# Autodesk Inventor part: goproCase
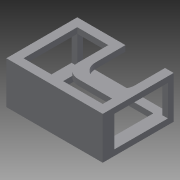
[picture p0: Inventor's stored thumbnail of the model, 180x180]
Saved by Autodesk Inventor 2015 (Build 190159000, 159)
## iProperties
Created: 2015-02
Part Number: goproCase
Material: Generic
Document SubType Name: Modeling
Designer: sungeun
Density: 1 g/cm^3
Appearance: Default
Author: sungeun
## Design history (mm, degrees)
sketch "Sketch1"
  geometry: L1 (-33.625, -24.75)-(33.625, -24.75); L2 (33.625, -24.75)-(33.625, 24.75); L3 (33.625, 24.75)-(-33.625, 24.75); L4 (-33.625, 24.75)-(-33.625, -24.75); L5 (-33.625, -24.75)-(33.625, 24.75); L6 (33.625, -24.75)-(-33.625, 24.75); L7 (-25.473, -18.75)-(25.473, -18.75); L8 (25.473, -18.75)-(25.473, 18.75); L9 (25.473, 18.75)-(-25.473, 18.75); L10 (-25.473, 18.75)-(-25.473, -18.75); L11 (-25.473, -18.75)-(25.473, 18.75); L12 (25.473, -18.75)-(-25.473, 18.75); 1 further point
  constraints: 24 end point, 4 midpoint, 4 parallel, 2 horizontal, 2 perpendicular, 1 point on line
  dimensions: "d0" = 67.25 distance of L3.end L2.end; "d1" = 49.5 distance of L2.end L1.end; "d2" = 6 distance between parallel lines of L9 L3
extrude "Extrusion1" new body sketch "Sketch1" distance "d3" = 4; taper "d4" = 0 deg
sketch "Sketch2"
  geometry: L1 (-33.625, 24.75)-(-29.625, 24.75); L2 (-29.625, 24.75)-(-29.625, 20.75); L3 (-29.625, 20.75)-(-33.625, 20.75); L4 (-33.625, 20.75)-(-33.625, 24.75); L5 (33.625, 24.75)-(29.625, 24.75); L6 (29.625, 24.75)-(29.625, 20.75); L7 (29.625, 20.75)-(33.625, 20.75); L8 (33.625, 20.75)-(33.625, 24.75); L9 (33.625, -24.75)-(33.625, -16.75); L10 (33.625, -24.75)-(33.625, 24.75) reference; L11 (33.625, -16.75)-(29.625, -16.75); L12 (29.625, -16.75)-(29.625, -20.75); L13 (-29.625, -20.75)-(-29.625, -16.75); L14 (-29.625, -16.75)-(-33.625, -16.75); L15 (-33.625, 24.75)-(-33.625, -24.75) reference; L16 (-33.625, -24.75)-(33.625, -24.75); L17 (-29.625, -20.75)-(29.625, -20.75); 1 further point
  constraints: 30 end point, 6 parallel, 5 point on line, 3 horizontal, 3 perpendicular
  dimensions: "d5" = 4 distance of L2.end L3.end; "d6" = 4 distance of L1.end L2.end; "d7" = 4 distance of L7.end L6.end; "d8" = 4 distance of L6.end L5.end; "d26" = 8 distance of L9.start L9.end; "d27" = 4 distance of L9.end L11.end; "d28" = 4 distance of L13.start L13.end; "d29" = 4 distance of L13.end L14.end
extrude "Extrusion2" join sketch "Sketch2" distance "d11" = 21.5; taper "d12" = 0 deg
sketch "Sketch9"
  geometry: L1 (50.947, 0)-(0, 0); L2 (0, 0)-(0, -4); L3 (0, -4)-(50.947, -4); L4 (50.947, -4)-(50.947, 0); 1 further point
  constraints: 8 end point, 2 parallel, 1 horizontal, 1 perpendicular
extrude "Extrusion7" join sketch "Sketch9" distance "d24" = 4; taper "d25" = 0 deg
sketch "Sketch10"
  geometry: L1 (33.625, 24.75)-(33.625, -24.75); L2 (33.625, -24.75)-(-33.625, -24.75); L3 (-33.625, -24.75)-(-33.625, 24.75); L4 (27.625, -18.75)-(-27.625, -18.75); L5 (-27.625, -18.75)-(-27.625, 18.75); L6 (0, 18.75)-(0, -6.25); L7 (0, -6.25)-(27.625, -6.25); L8 (-6, 18.75)-(-6, -12.25); L9 (-6, -12.25)-(27.625, -12.25); L10 (-27.625, 18.75)-(-6, 18.75); L11 (0, 18.75)-(27.625, 18.75); L12 (27.625, 18.75)-(27.625, -6.25); L13 (27.625, -12.25)-(27.625, -18.75); L14 (0, 18.75)-(0, 24.75); L15 (27.625, 18.75)-(27.625, 24.75); L16 (29.625, 24.75)-(-29.625, 24.75) reference; L17 (-33.625, 24.75)-(0, 24.75); L18 (27.625, 24.75)-(33.625, 24.75); 1 further point
  constraints: 34 end point, 8 parallel, 8 perpendicular, 4 horizontal, 1 point on line, 1 vertical, 1 other
  dimensions: "d31" = 6 distance between parallel lines of L2 L4; "d33" = 6 distance between parallel lines of L3 L5; "d39" = 25 distance of L6.start L6.end; "d40" = 6 distance between parallel lines of L6 L8
extrude "Extrusion8" join sketch "Sketch10" distance "d34" = 4; taper "d35" = 0 deg
fillet "Fillet1" dims "d41" = 10
fillet "Fillet2" dims "d42" = 10
body "Solid1"
other parameters: "d30" = 6, "d32" = 6
